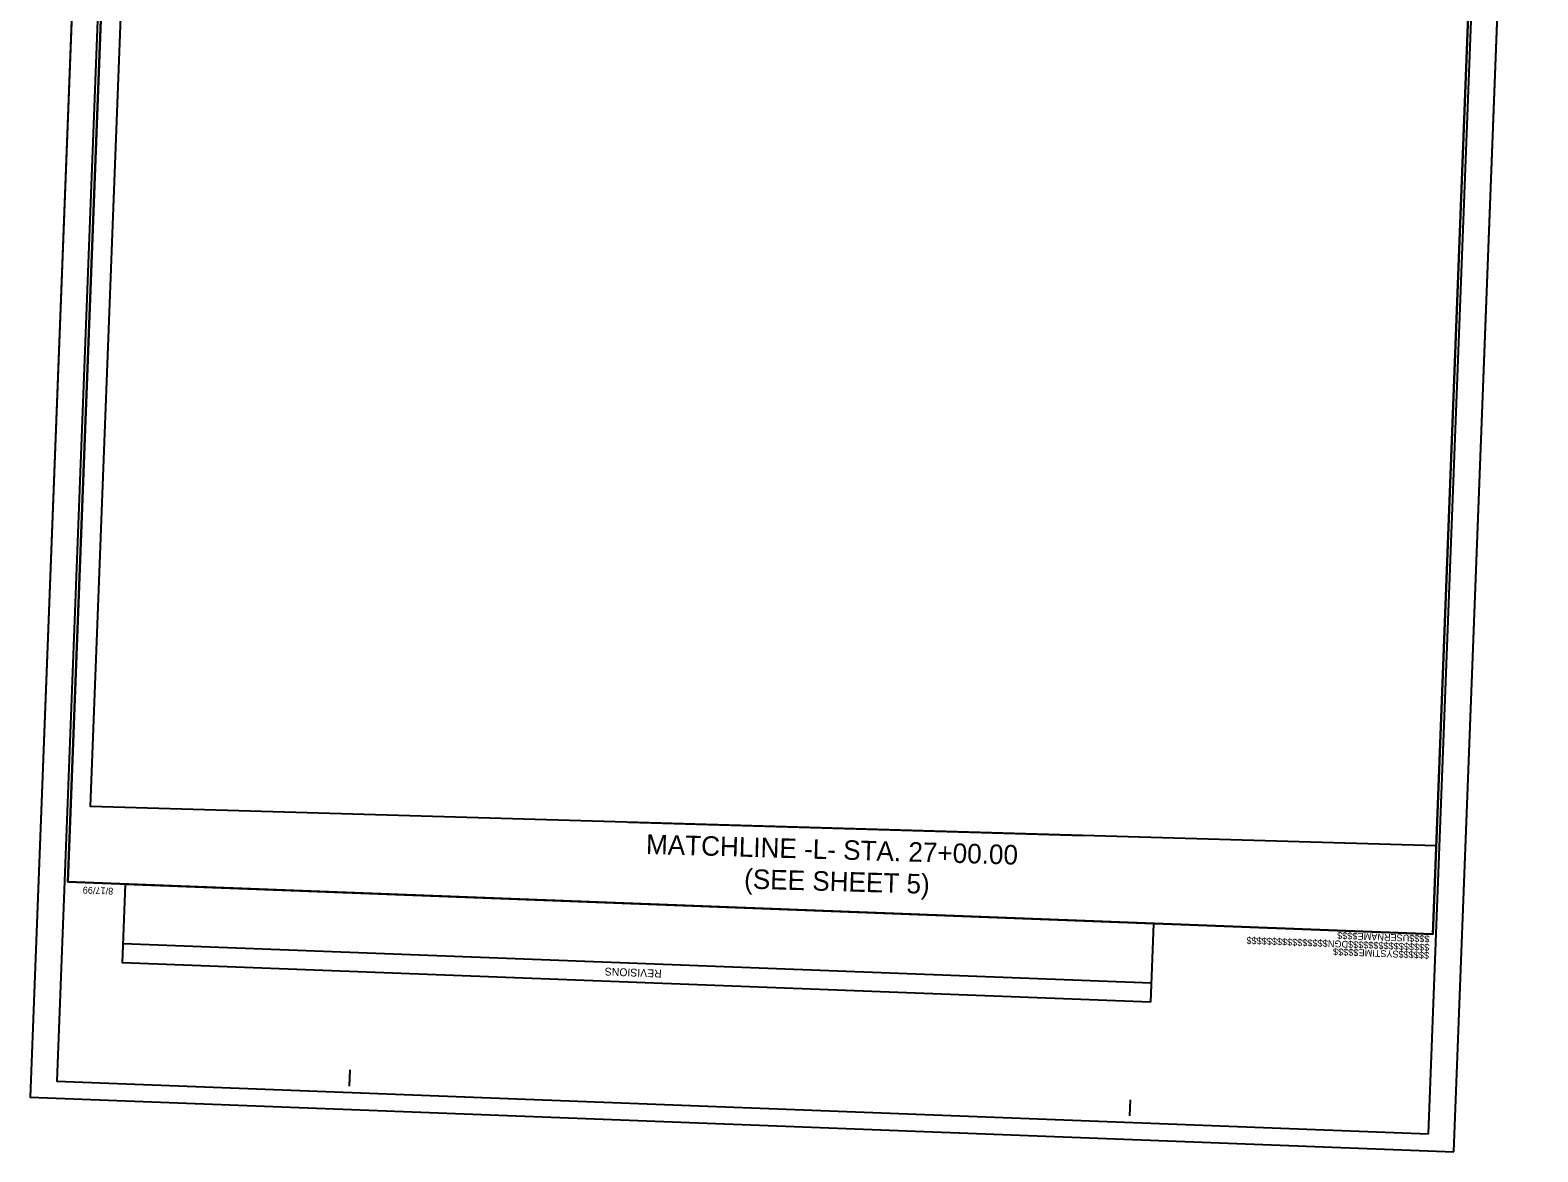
# Model space of a CAD drawing. Extents: x 2097083 to 2098242, y 681809 to 688195.
# Drawn here: x 2097083 to 2098242, y 686471 to 687333 of the extents above; entities that cross this region are included whole.
import ezdxf

# ---------------------------------------------------------------- set-up
doc = ezdxf.new("R2010")
doc.units = 0
for name, color, linetype in [('Matchline', 7, 'Continuous'), ('Matchline Text', 7, 'Continuous'), ('Scratch_Level_6', 7, 'Continuous'), ('Sheet Block Revision CELL', 7, 'Continuous'), ('Sheet Cutting Line CELL', 7, 'Continuous'), ('Sheet Plan CELL', 7, 'Continuous'), ('Sheet Plot Border Inside CELL', 7, 'Continuous'), ('Sheet Plot Border Outside CELL', 7, 'Continuous')]:
    doc.layers.add(name, color=color, linetype=linetype)

msp = doc.modelspace()

# ---------------------------------------------------------------- linework, layer by layer
at = {"layer": 'Matchline'}
msp.add_line((2097543.1, 686723.9), (2097892.9, 686713.8), dxfattribs=at)
at = {"layer": 'Scratch_Level_6'}
msp.add_lwpolyline([(2098163.9, 686705.9), (2097129.6, 686735.9), (2097169.5, 687776.6), (2097195.7, 687775.6), (2097203.4, 687975.5), (2097338.1, 687970.3), (2097342.5, 688084.2), (2098215.5, 688050.7)], close=True, dxfattribs=at)
at = {"layer": 'Sheet Block Revision CELL'}
msp.add_line((2097944.7, 686600.1), (2097154.7, 686630.4), dxfattribs=at)
msp.add_lwpolyline([(2097944.2, 686585.6), (2097154.1, 686615.9), (2097156.4, 686676.4), (2097946.5, 686646.1)], close=True, dxfattribs=at)
at = {"layer": 'Sheet Cutting Line CELL'}
for p, q in [((2097147.8, 688194.8), (2097083.2, 686512.5)), ((2098177.4, 686470.6), (2098242, 688152.8)), ((2097083.2, 686512.5), (2098177.4, 686470.6))]:
    msp.add_line(p, q, dxfattribs=at)
at = {"layer": 'Sheet Plan CELL'}
for p, q in [((2097112.1, 686678), (2097112.1, 686678)), ((2098161.3, 686637.8), (2098161.3, 686637.8)), ((2097328.8, 686521.1), (2097329.2, 686533.6)), ((2097928.3, 686498.2), (2097928.8, 686510.6))]:
    msp.add_line(p, q, dxfattribs=at)
for points in [[(2097169.6, 688177), (2097112.1, 686678), (2098161.3, 686637.8), (2098218.8, 688136.7)], [(2098161.3, 686637.8), (2097112.1, 686678), (2097161.9, 687977.1), (2097311.9, 687971.3), (2097319.5, 688171.2), (2098218.8, 688136.7)]]:
    msp.add_lwpolyline(points, close=True, dxfattribs=at)
at = {"layer": 'Sheet Plot Border Inside CELL'}
msp.add_lwpolyline([(2098158, 686484.3), (2098221.8, 688149.1), (2097167.6, 688189.5), (2097103.7, 686524.8)], close=True, dxfattribs=at)
at = {"layer": 'Sheet Plot Border Outside CELL'}
msp.add_lwpolyline([(2098177.4, 686470.6), (2098242, 688152.8), (2097147.8, 688194.8), (2097083.2, 686512.5)], close=True, dxfattribs=at)

# ---------------------------------------------------------------- texts
at = {"layer": 'Matchline Text'}
for s, p in [('MATCHLINE -L- STA. 27+00.00', (2097556.4, 686699.6)), ('(SEE SHEET 5)', (2097631.8, 686673))]:
    msp.add_text(s, height=15, rotation=358.3348, dxfattribs=at).set_placement(p)
at = {"layer": 'Sheet Block Revision CELL'}
msp.add_text('REVISIONS', height=6, rotation=177.8037, dxfattribs=at).set_placement((2097568.7, 686610.5))
at = {"layer": 'Sheet Plan CELL'}
for s, p in [('8/17/99', (2097147.2, 686673.5)), ('$$$$$$$$$$$$$$$$DGN$$$$$$$$$$$$$$$$', (2098158.7, 686630.3)), ('$$$$USERNAME$$$$', (2098158.9, 686636.8)), ('$$$$$$SYSTIME$$$$$', (2098158.5, 686624.2))]:
    msp.add_text(s, height=5.25, rotation=177.8037, dxfattribs=at).set_placement(p)

doc.saveas('drawing.dxf')
